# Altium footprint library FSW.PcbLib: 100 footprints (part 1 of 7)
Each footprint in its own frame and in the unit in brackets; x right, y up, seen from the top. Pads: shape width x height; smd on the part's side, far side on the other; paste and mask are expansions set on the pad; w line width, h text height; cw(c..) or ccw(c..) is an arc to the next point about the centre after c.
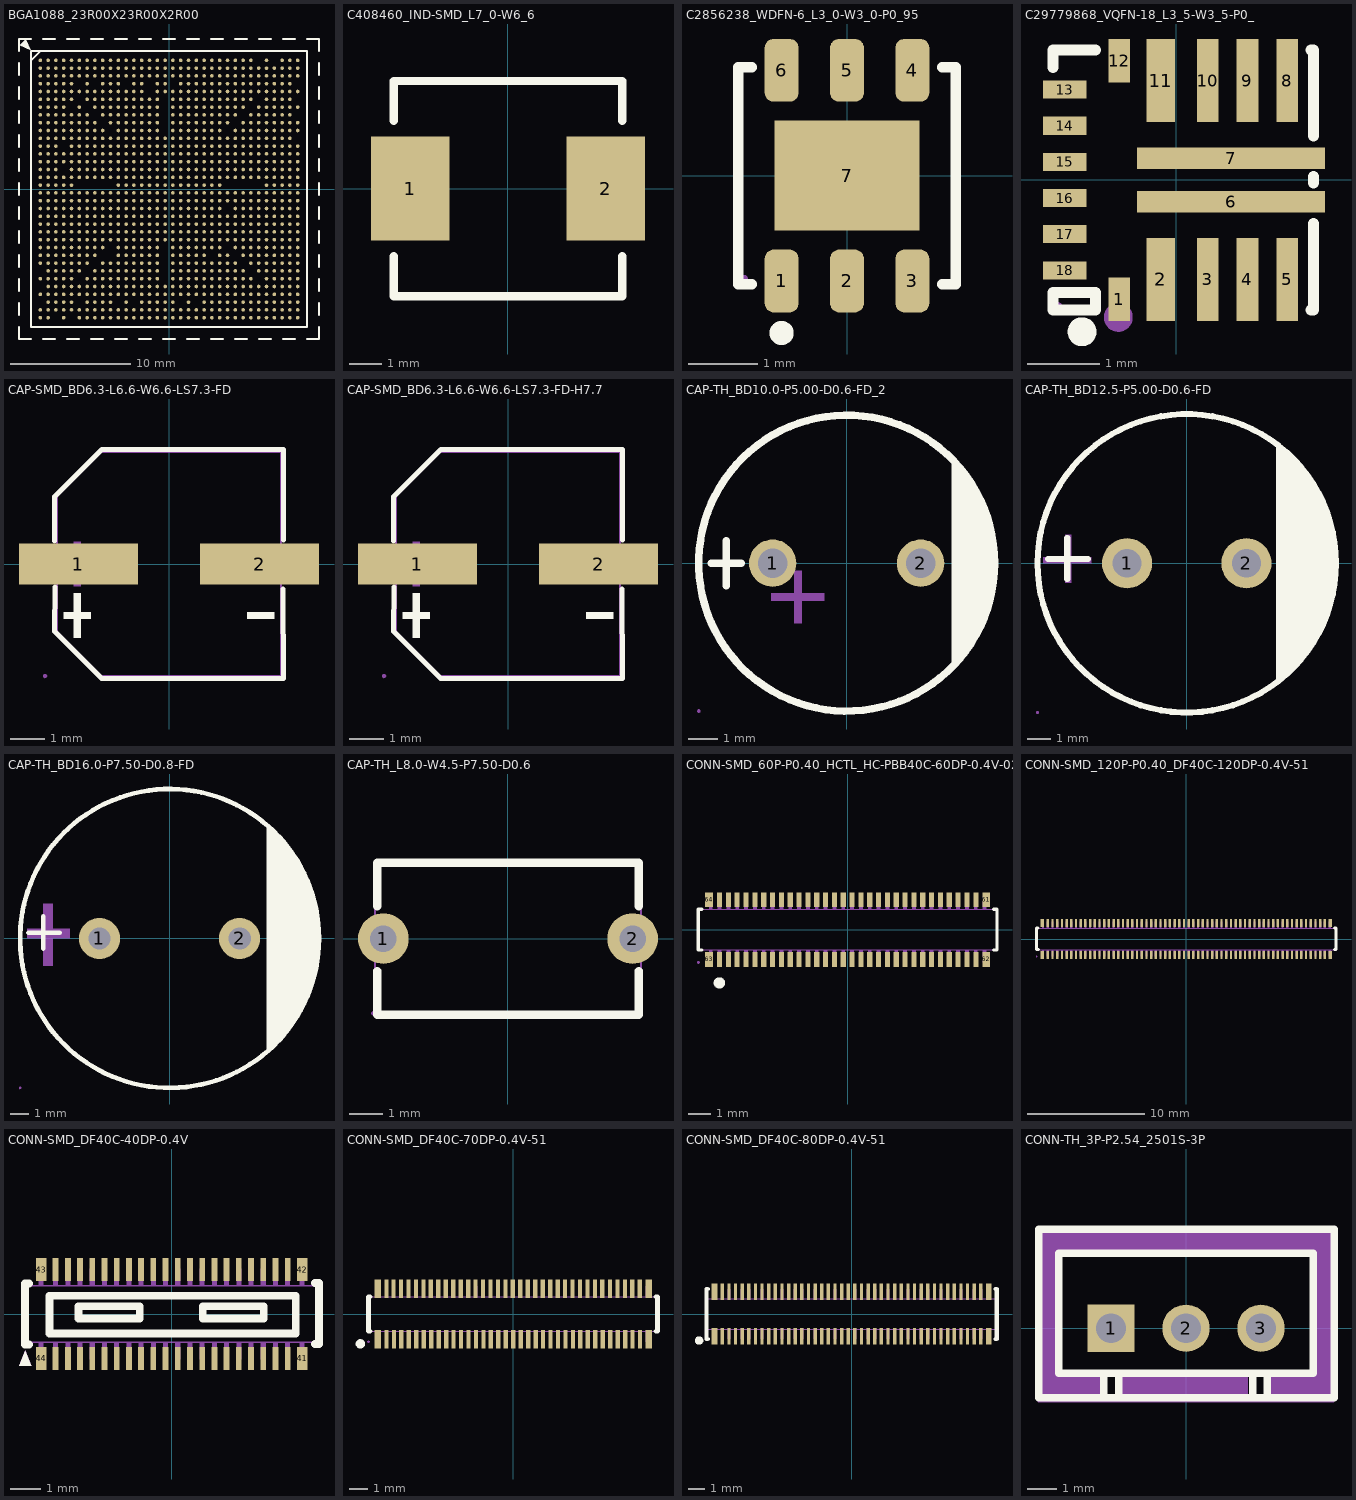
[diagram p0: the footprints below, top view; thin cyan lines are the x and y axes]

## BGA1088_23R00X23R00X2R00 [mm]
pads (1088):
  round 0.3 smd paste+0.102 mask+0.025: A1(-10.725,10.725) A2(-10.075,10.725) A3(-9.425,10.725) A4(-8.775,10.725) A5(-8.125,10.725) A6(-7.475,10.725) A7(-6.825,10.725) A8(-6.175,10.725) A9(-5.525,10.725) A10(-4.875,10.725) A11(-4.225,10.725) A12(-3.575,10.725) A13(-2.925,10.725) A14(-2.275,10.725) A15(-1.625,10.725) A16(-0.975,10.725) A17(-0.325,10.725) A18(0.325,10.725) A19(0.975,10.725) A20(1.625,10.725) A21(2.275,10.725) A22(2.925,10.725) A23(3.575,10.725) A24(4.225,10.725) A25(4.875,10.725) A26(5.525,10.725) A27(6.175,10.725) A28(6.825,10.725) A30(8.125,10.725) A32(9.425,10.725) A33(10.075,10.725) A34(10.725,10.725) AA1(-10.725,-2.275) AA2(-10.075,-2.275) AA3(-9.425,-2.275) AA4(-8.775,-2.275) AA5(-8.125,-2.275) AA6(-7.475,-2.275) AA7(-6.825,-2.275) AA8(-6.175,-2.275) AA9(-5.525,-2.275) AA10(-4.875,-2.275) AA11(-4.225,-2.275) AA12(-3.575,-2.275) AA13(-2.925,-2.275) AA14(-2.275,-2.275) AA15(-1.625,-2.275) AA16(-0.975,-2.275) AA17(-0.325,-2.275) AA18(0.325,-2.275) AA19(0.975,-2.275) AA20(1.625,-2.275) AA21(2.275,-2.275) AA22(2.925,-2.275) AA23(3.575,-2.275) AA24(4.225,-2.275) AA25(4.875,-2.275) AA26(5.525,-2.275) AA27(6.175,-2.275) AA28(6.825,-2.275) AA29(7.475,-2.275) AA30(8.125,-2.275) AA31(8.775,-2.275) AA32(9.425,-2.275) AA33(10.075,-2.275) AA34(10.725,-2.275) AB1(-10.725,-2.925) AB2(-10.075,-2.925) AB3(-9.425,-2.925) AB4(-8.775,-2.925) AB5(-8.125,-2.925) AB6(-7.475,-2.925) AB7(-6.825,-2.925) AB8(-6.175,-2.925) AB9(-5.525,-2.925) AB10(-4.875,-2.925) AB11(-4.225,-2.925) AB12(-3.575,-2.925) AB13(-2.925,-2.925) AB14(-2.275,-2.925) AB15(-1.625,-2.925) AB16(-0.975,-2.925) AB17(-0.325,-2.925) AB18(0.325,-2.925) AB19(0.975,-2.925) AB20(1.625,-2.925) AB21(2.275,-2.925) AB22(2.925,-2.925) AB23(3.575,-2.925) AB24(4.225,-2.925) AB25(4.875,-2.925) AB26(5.525,-2.925) AB27(6.175,-2.925) AB28(6.825,-2.925) AB29(7.475,-2.925) AB30(8.125,-2.925) AB31(8.775,-2.925) AB32(9.425,-2.925) AB33(10.075,-2.925) AB34(10.725,-2.925) AC1(-10.725,-3.575) AC2(-10.075,-3.575) AC3(-9.425,-3.575) AC4(-8.775,-3.575) AC5(-8.125,-3.575) AC6(-7.475,-3.575) AC7(-6.825,-3.575) AC8(-6.175,-3.575) AC9(-5.525,-3.575) AC10(-4.875,-3.575) AC11(-4.225,-3.575) AC12(-3.575,-3.575) AC13(-2.925,-3.575) AC14(-2.275,-3.575) AC15(-1.625,-3.575) AC16(-0.975,-3.575) AC17(-0.325,-3.575) AC18(0.325,-3.575) AC19(0.975,-3.575) AC20(1.625,-3.575) AC21(2.275,-3.575) AC22(2.925,-3.575) AC23(3.575,-3.575) AC24(4.225,-3.575) AC25(4.875,-3.575) AC26(5.525,-3.575) AC27(6.175,-3.575) AC28(6.825,-3.575) AC29(7.475,-3.575) AC30(8.125,-3.575) AC31(8.775,-3.575) AC32(9.425,-3.575) AC33(10.075,-3.575) AC34(10.725,-3.575) AD1(-10.725,-4.225) AD2(-10.075,-4.225) AD3(-9.425,-4.225) AD4(-8.775,-4.225) AD5(-8.125,-4.225) AD6(-7.475,-4.225) AD7(-6.825,-4.225) AD8(-6.175,-4.225) AD9(-5.525,-4.225) AD10(-4.875,-4.225) AD11(-4.225,-4.225) AD12(-3.575,-4.225) AD13(-2.925,-4.225) AD14(-2.275,-4.225) AD15(-1.625,-4.225) AD16(-0.975,-4.225) AD17(-0.325,-4.225) AD18(0.325,-4.225) AD19(0.975,-4.225) AD20(1.625,-4.225) AD21(2.275,-4.225) AD22(2.925,-4.225) AD23(3.575,-4.225) AD24(4.225,-4.225) AD25(4.875,-4.225) AD26(5.525,-4.225) AD27(6.175,-4.225) AD28(6.825,-4.225) AD29(7.475,-4.225) AD30(8.125,-4.225) AD31(8.775,-4.225) AD32(9.425,-4.225) AD33(10.075,-4.225) AD34(10.725,-4.225) AE1(-10.725,-4.875) AE2(-10.075,-4.875) AE3(-9.425,-4.875) AE4(-8.775,-4.875) AE5(-8.125,-4.875) AE6(-7.475,-4.875) AE7(-6.825,-4.875) AE8(-6.175,-4.875) AE9(-5.525,-4.875) AE11(-4.225,-4.875) AE12(-3.575,-4.875) AE13(-2.925,-4.875) AE14(-2.275,-4.875) AE15(-1.625,-4.875) AE16(-0.975,-4.875) AE18(0.325,-4.875) AE19(0.975,-4.875) AE20(1.625,-4.875) AE21(2.275,-4.875) AE22(2.925,-4.875) AE23(3.575,-4.875) AE24(4.225,-4.875) AE26(5.525,-4.875) AE27(6.175,-4.875) AE28(6.825,-4.875) AE29(7.475,-4.875) AE30(8.125,-4.875) AE31(8.775,-4.875) AE32(9.425,-4.875) AE33(10.075,-4.875) AE34(10.725,-4.875) AF1(-10.725,-5.525) AF2(-10.075,-5.525) AF3(-9.425,-5.525) AF4(-8.775,-5.525) AF5(-8.125,-5.525) AF6(-7.475,-5.525) AF7(-6.825,-5.525) AF8(-6.175,-5.525) AF11(-4.225,-5.525) AF12(-3.575,-5.525) AF13(-2.925,-5.525) AF14(-2.275,-5.525) AF15(-1.625,-5.525) AF16(-0.975,-5.525) AF18(0.325,-5.525) AF19(0.975,-5.525) AF20(1.625,-5.525) AF21(2.275,-5.525) AF22(2.925,-5.525) AF24(4.225,-5.525) AF25(4.875,-5.525) AF27(6.175,-5.525) AF28(6.825,-5.525) AF29(7.475,-5.525) AF30(8.125,-5.525) AF31(8.775,-5.525) AF32(9.425,-5.525) AF33(10.075,-5.525) AF34(10.725,-5.525) AG1(-10.725,-6.175) AG2(-10.075,-6.175) AG3(-9.425,-6.175) AG4(-8.775,-6.175) AG5(-8.125,-6.175) AG6(-7.475,-6.175) AG7(-6.825,-6.175) AG9(-5.525,-6.175) AG10(-4.875,-6.175) AG11(-4.225,-6.175) AG12(-3.575,-6.175) AG13(-2.925,-6.175) AG14(-2.275,-6.175) AG15(-1.625,-6.175) AG16(-0.975,-6.175) AG18(0.325,-6.175) AG19(0.975,-6.175) AG20(1.625,-6.175) AG21(2.275,-6.175) AG22(2.925,-6.175) AG23(3.575,-6.175) AG24(4.225,-6.175) AG25(4.875,-6.175) AG26(5.525,-6.175) AG28(6.825,-6.175) AG29(7.475,-6.175) AG30(8.125,-6.175) AG31(8.775,-6.175) AG32(9.425,-6.175) AG33(10.075,-6.175) AG34(10.725,-6.175) AH2(-10.075,-6.825) AH3(-9.425,-6.825) AH4(-8.775,-6.825) AH5(-8.125,-6.825) AH6(-7.475,-6.825) AH8(-6.175,-6.825) AH9(-5.525,-6.825) AH10(-4.875,-6.825) AH11(-4.225,-6.825) AH12(-3.575,-6.825) AH13(-2.925,-6.825) AH14(-2.275,-6.825) AH15(-1.625,-6.825) AH16(-0.975,-6.825) AH18(0.325,-6.825) AH19(0.975,-6.825) AH20(1.625,-6.825) AH21(2.275,-6.825) AH22(2.925,-6.825) AH23(3.575,-6.825) AH24(4.225,-6.825) AH25(4.875,-6.825) AH26(5.525,-6.825) AH27(6.175,-6.825) AH29(7.475,-6.825) AH30(8.125,-6.825) AH31(8.775,-6.825) AH32(9.425,-6.825) AH33(10.075,-6.825) AH34(10.725,-6.825) AJ1(-10.725,-7.475) AJ2(-10.075,-7.475) AJ3(-9.425,-7.475) AJ4(-8.775,-7.475) AJ5(-8.125,-7.475) AJ7(-6.825,-7.475) AJ8(-6.175,-7.475) AJ9(-5.525,-7.475) AJ10(-4.875,-7.475) AJ11(-4.225,-7.475) AJ12(-3.575,-7.475) AJ13(-2.925,-7.475) AJ14(-2.275,-7.475) AJ15(-1.625,-7.475) AJ16(-0.975,-7.475) AJ18(0.325,-7.475) AJ19(0.975,-7.475) AJ20(1.625,-7.475) AJ21(2.275,-7.475) AJ22(2.925,-7.475) AJ23(3.575,-7.475) AJ24(4.225,-7.475) AJ25(4.875,-7.475) AJ26(5.525,-7.475) AJ27(6.175,-7.475) AJ28(6.825,-7.475) AJ30(8.125,-7.475) AJ31(8.775,-7.475) AJ32(9.425,-7.475) AJ33(10.075,-7.475) AJ34(10.725,-7.475) AK2(-10.075,-8.125) AK3(-9.425,-8.125) AK4(-8.775,-8.125) AK5(-8.125,-8.125) AK6(-7.475,-8.125) AK7(-6.825,-8.125) AK8(-6.175,-8.125) AK9(-5.525,-8.125) AK10(-4.875,-8.125) AK11(-4.225,-8.125) AK12(-3.575,-8.125) AK13(-2.925,-8.125) AK14(-2.275,-8.125) AK15(-1.625,-8.125) AK16(-0.975,-8.125) AK17(-0.325,-8.125) AK18(0.325,-8.125) AK19(0.975,-8.125) AK20(1.625,-8.125) AK21(2.275,-8.125) AK22(2.925,-8.125) AK23(3.575,-8.125) AK24(4.225,-8.125) AK25(4.875,-8.125) AK26(5.525,-8.125) AK27(6.175,-8.125) AK28(6.825,-8.125) AK29(7.475,-8.125) AK30(8.125,-8.125) AK31(8.775,-8.125) AK32(9.425,-8.125) AK33(10.075,-8.125) AK34(10.725,-8.125) AL1(-10.725,-8.775) AL2(-10.075,-8.775) AL3(-9.425,-8.775) AL4(-8.775,-8.775) AL5(-8.125,-8.775) AL6(-7.475,-8.775) AL7(-6.825,-8.775) AL8(-6.175,-8.775) AL9(-5.525,-8.775) AL10(-4.875,-8.775) AL11(-4.225,-8.775) AL12(-3.575,-8.775) AL13(-2.925,-8.775) AL14(-2.275,-8.775) AL15(-1.625,-8.775) AL16(-0.975,-8.775) AL17(-0.325,-8.775) AL18(0.325,-8.775) AL19(0.975,-8.775) AL20(1.625,-8.775) AL21(2.275,-8.775) AL22(2.925,-8.775) AL23(3.575,-8.775) AL24(4.225,-8.775) AL25(4.875,-8.775) AL26(5.525,-8.775) AL27(6.175,-8.775) AL28(6.825,-8.775) AL29(7.475,-8.775) AL30(8.125,-8.775) AL31(8.775,-8.775) AL32(9.425,-8.775) AL33(10.075,-8.775) AL34(10.725,-8.775) AM2(-10.075,-9.425) AM3(-9.425,-9.425) AM4(-8.775,-9.425) AM5(-8.125,-9.425) AM7(-6.825,-9.425) AM8(-6.175,-9.425) AM9(-5.525,-9.425) AM10(-4.875,-9.425) AM12(-3.575,-9.425) AM14(-2.275,-9.425) AM15(-1.625,-9.425) AM16(-0.975,-9.425) AM17(-0.325,-9.425) AM18(0.325,-9.425) AM20(1.625,-9.425) AM22(2.925,-9.425) AM23(3.575,-9.425) AM24(4.225,-9.425) AM25(4.875,-9.425) AM26(5.525,-9.425) AM27(6.175,-9.425) AM28(6.825,-9.425) AM29(7.475,-9.425) AM30(8.125,-9.425) AM31(8.775,-9.425) AM32(9.425,-9.425) AM33(10.075,-9.425) AM34(10.725,-9.425) AN1(-10.725,-10.075) AN2(-10.075,-10.075) AN3(-9.425,-10.075) AN4(-8.775,-10.075) AN5(-8.125,-10.075) AN6(-7.475,-10.075) AN7(-6.825,-10.075) AN8(-6.175,-10.075) AN9(-5.525,-10.075) AN10(-4.875,-10.075) AN11(-4.225,-10.075) AN12(-3.575,-10.075) AN13(-2.925,-10.075) AN14(-2.275,-10.075) AN15(-1.625,-10.075) AN16(-0.975,-10.075) AN17(-0.325,-10.075) AN18(0.325,-10.075) AN19(0.975,-10.075) AN20(1.625,-10.075) AN21(2.275,-10.075) AN22(2.925,-10.075) AN23(3.575,-10.075) AN24(4.225,-10.075) AN25(4.875,-10.075) AN26(5.525,-10.075) AN27(6.175,-10.075) AN28(6.825,-10.075) AN29(7.475,-10.075) AN30(8.125,-10.075) AN31(8.775,-10.075) AN32(9.425,-10.075) AN33(10.075,-10.075) AN34(10.725,-10.075) AP1(-10.725,-10.725) AP2(-10.075,-10.725) AP4(-8.775,-10.725) AP6(-7.475,-10.725) AP7(-6.825,-10.725) AP8(-6.175,-10.725) AP9(-5.525,-10.725) AP10(-4.875,-10.725) AP11(-4.225,-10.725) AP12(-3.575,-10.725) AP13(-2.925,-10.725) AP14(-2.275,-10.725) AP15(-1.625,-10.725) AP16(-0.975,-10.725) AP17(-0.325,-10.725) AP18(0.325,-10.725) AP19(0.975,-10.725) AP20(1.625,-10.725) AP21(2.275,-10.725) AP22(2.925,-10.725) AP23(3.575,-10.725) AP24(4.225,-10.725) AP25(4.875,-10.725) AP26(5.525,-10.725) AP27(6.175,-10.725) AP28(6.825,-10.725) AP29(7.475,-10.725) AP30(8.125,-10.725) AP31(8.775,-10.725) AP32(9.425,-10.725) AP33(10.075,-10.725) AP34(10.725,-10.725) B1(-10.725,10.075) B2(-10.075,10.075) B3(-9.425,10.075) B4(-8.775,10.075) B5(-8.125,10.075) B6(-7.475,10.075) B7(-6.825,10.075) B8(-6.175,10.075) B9(-5.525,10.075) B10(-4.875,10.075) B11(-4.225,10.075) B12(-3.575,10.075) B13(-2.925,10.075) B14(-2.275,10.075) B15(-1.625,10.075) B16(-0.975,10.075) B17(-0.325,10.075) B18(0.325,10.075) B19(0.975,10.075) B20(1.625,10.075) B21(2.275,10.075) B22(2.925,10.075) B23(3.575,10.075) B24(4.225,10.075) B25(4.875,10.075) B26(5.525,10.075) B27(6.175,10.075) B28(6.825,10.075) B29(7.475,10.075) B30(8.125,10.075) B31(8.775,10.075) B32(9.425,10.075) B33(10.075,10.075) B34(10.725,10.075) C1(-10.725,9.425) C2(-10.075,9.425) C3(-9.425,9.425) C4(-8.775,9.425) C5(-8.125,9.425) C6(-7.475,9.425) C7(-6.825,9.425) C8(-6.175,9.425) C9(-5.525,9.425) C10(-4.875,9.425) C11(-4.225,9.425) C12(-3.575,9.425) C13(-2.925,9.425) C14(-2.275,9.425) C15(-1.625,9.425) C16(-0.975,9.425) C17(-0.325,9.425) C18(0.325,9.425) C19(0.975,9.425) C20(1.625,9.425) C21(2.275,9.425) C22(2.925,9.425) C23(3.575,9.425) C24(4.225,9.425) C25(4.875,9.425) C26(5.525,9.425) C27(6.175,9.425) C28(6.825,9.425) C29(7.475,9.425) C30(8.125,9.425) C31(8.775,9.425) C32(9.425,9.425) C33(10.075,9.425) C34(10.725,9.425) D1(-10.725,8.775) D2(-10.075,8.775) D3(-9.425,8.775) D4(-8.775,8.775) D5(-8.125,8.775) D7(-6.825,8.775) D9(-5.525,8.775) D10(-4.875,8.775) D11(-4.225,8.775) D13(-2.925,8.775) D14(-2.275,8.775) D16(-0.975,8.775) D17(-0.325,8.775) D19(0.975,8.775) D20(1.625,8.775) D21(2.275,8.775) D22(2.925,8.775) D23(3.575,8.775) D24(4.225,8.775) D25(4.875,8.775) D26(5.525,8.775) D27(6.175,8.775) D28(6.825,8.775) D29(7.475,8.775) D30(8.125,8.775) D31(8.775,8.775) D32(9.425,8.775) D33(10.075,8.775) E1(-10.725,8.125) E2(-10.075,8.125) E3(-9.425,8.125) E4(-8.775,8.125) E5(-8.125,8.125) E6(-7.475,8.125) E7(-6.825,8.125) E8(-6.175,8.125) E9(-5.525,8.125) E10(-4.875,8.125) E11(-4.225,8.125) E12(-3.575,8.125) E13(-2.925,8.125) E14(-2.275,8.125) E16(-0.975,8.125) E17(-0.325,8.125) E18(0.325,8.125) E19(0.975,8.125) E20(1.625,8.125) E21(2.275,8.125) E22(2.925,8.125) E23(3.575,8.125) E24(4.225,8.125) E25(4.875,8.125) E26(5.525,8.125) E27(6.175,8.125) E28(6.825,8.125) E29(7.475,8.125) E30(8.125,8.125) E31(8.775,8.125) E32(9.425,8.125) E33(10.075,8.125) E34(10.725,8.125) F1(-10.725,7.475) F2(-10.075,7.475) F3(-9.425,7.475) F4(-8.775,7.475) F5(-8.125,7.475) F7(-6.825,7.475) F8(-6.175,7.475) F9(-5.525,7.475) F10(-4.875,7.475) F11(-4.225,7.475) F12(-3.575,7.475) F13(-2.925,7.475) F14(-2.275,7.475) F15(-1.625,7.475) F16(-0.975,7.475) F18(0.325,7.475) F19(0.975,7.475) F20(1.625,7.475) F21(2.275,7.475) F22(2.925,7.475) F23(3.575,7.475) F24(4.225,7.475) F25(4.875,7.475) F26(5.525,7.475) F27(6.175,7.475) F28(6.825,7.475) F30(8.125,7.475) F31(8.775,7.475) F32(9.425,7.475) F33(10.075,7.475) G1(-10.725,6.825) G2(-10.075,6.825) G3(-9.425,6.825) G4(-8.775,6.825) G6(-7.475,6.825) G8(-6.175,6.825) G9(-5.525,6.825) G10(-4.875,6.825) G11(-4.225,6.825) G12(-3.575,6.825) G13(-2.925,6.825) G14(-2.275,6.825) G15(-1.625,6.825) G16(-0.975,6.825) G18(0.325,6.825) G19(0.975,6.825) G20(1.625,6.825) G21(2.275,6.825) G22(2.925,6.825) G23(3.575,6.825) G24(4.225,6.825) G25(4.875,6.825) G26(5.525,6.825) G27(6.175,6.825) G29(7.475,6.825) G30(8.125,6.825) G31(8.775,6.825) G32(9.425,6.825) G33(10.075,6.825) G34(10.725,6.825) H1(-10.725,6.175) H2(-10.075,6.175) H3(-9.425,6.175) H4(-8.775,6.175) H5(-8.125,6.175) H6(-7.475,6.175) H7(-6.825,6.175) H9(-5.525,6.175) H10(-4.875,6.175) H11(-4.225,6.175) H12(-3.575,6.175) H13(-2.925,6.175) H14(-2.275,6.175) H15(-1.625,6.175) H16(-0.975,6.175) H18(0.325,6.175) H19(0.975,6.175) H20(1.625,6.175) H21(2.275,6.175) H22(2.925,6.175) H23(3.575,6.175) H24(4.225,6.175) H25(4.875,6.175) H26(5.525,6.175) H28(6.825,6.175) H29(7.475,6.175) H30(8.125,6.175) H31(8.775,6.175) H32(9.425,6.175) H33(10.075,6.175) J1(-10.725,5.525) J2(-10.075,5.525) J3(-9.425,5.525) J4(-8.775,5.525) J5(-8.125,5.525) J6(-7.475,5.525) J7(-6.825,5.525) J8(-6.175,5.525) J10(-4.875,5.525) J11(-4.225,5.525) J12(-3.575,5.525) J13(-2.925,5.525) J14(-2.275,5.525) J15(-1.625,5.525) J16(-0.975,5.525) J18(0.325,5.525) J19(0.975,5.525) J20(1.625,5.525) J21(2.275,5.525) J22(2.925,5.525) J23(3.575,5.525) J24(4.225,5.525) J25(4.875,5.525) J27(6.175,5.525) J28(6.825,5.525) J29(7.475,5.525) J30(8.125,5.525) J31(8.775,5.525) J32(9.425,5.525) J33(10.075,5.525) J34(10.725,5.525) K1(-10.725,4.875) K2(-10.075,4.875) K3(-9.425,4.875) K4(-8.775,4.875) K5(-8.125,4.875) K6(-7.475,4.875) K7(-6.825,4.875) K8(-6.175,4.875) K9(-5.525,4.875) K11(-4.225,4.875) K12(-3.575,4.875) K13(-2.925,4.875) K14(-2.275,4.875) K15(-1.625,4.875) K16(-0.975,4.875) K18(0.325,4.875) K19(0.975,4.875) K20(1.625,4.875) K21(2.275,4.875) K22(2.925,4.875) K23(3.575,4.875) K24(4.225,4.875) K26(5.525,4.875) K27(6.175,4.875) K28(6.825,4.875) K29(7.475,4.875) K30(8.125,4.875) K31(8.775,4.875) K32(9.425,4.875) K33(10.075,4.875) K34(10.725,4.875) L1(-10.725,4.225) L2(-10.075,4.225) L3(-9.425,4.225) L4(-8.775,4.225) L5(-8.125,4.225) L6(-7.475,4.225) L7(-6.825,4.225) L8(-6.175,4.225) L9(-5.525,4.225) L10(-4.875,4.225) L11(-4.225,4.225) L12(-3.575,4.225) L13(-2.925,4.225) L14(-2.275,4.225) L15(-1.625,4.225) L16(-0.975,4.225) L17(-0.325,4.225) L18(0.325,4.225) L19(0.975,4.225) L20(1.625,4.225) L21(2.275,4.225) L22(2.925,4.225) L23(3.575,4.225) L24(4.225,4.225) L25(4.875,4.225) L26(5.525,4.225) L27(6.175,4.225) L28(6.825,4.225) L29(7.475,4.225) L30(8.125,4.225) L31(8.775,4.225) L32(9.425,4.225) L33(10.075,4.225) M1(-10.725,3.575) M2(-10.075,3.575) M3(-9.425,3.575) M5(-8.125,3.575) M6(-7.475,3.575) M7(-6.825,3.575) M8(-6.175,3.575) M9(-5.525,3.575) M10(-4.875,3.575) M11(-4.225,3.575) M12(-3.575,3.575) M13(-2.925,3.575) M14(-2.275,3.575) M15(-1.625,3.575) M16(-0.975,3.575) M17(-0.325,3.575) M18(0.325,3.575) M19(0.975,3.575) M20(1.625,3.575) M21(2.275,3.575) M22(2.925,3.575) M23(3.575,3.575) M24(4.225,3.575) M25(4.875,3.575) M26(5.525,3.575) M27(6.175,3.575) M28(6.825,3.575) M29(7.475,3.575) M30(8.125,3.575) M31(8.775,3.575) M32(9.425,3.575) M33(10.075,3.575) M34(10.725,3.575) N1(-10.725,2.925) N2(-10.075,2.925) N3(-9.425,2.925) N4(-8.775,2.925) N5(-8.125,2.925) N6(-7.475,2.925) N7(-6.825,2.925) N8(-6.175,2.925) N9(-5.525,2.925) N10(-4.875,2.925) N11(-4.225,2.925) N12(-3.575,2.925) N13(-2.925,2.925) N14(-2.275,2.925) N15(-1.625,2.925) N16(-0.975,2.925) N17(-0.325,2.925) N18(0.325,2.925) N19(0.975,2.925) N20(1.625,2.925) N21(2.275,2.925) N22(2.925,2.925) N23(3.575,2.925) N24(4.225,2.925) N25(4.875,2.925) N26(5.525,2.925) N27(6.175,2.925) N28(6.825,2.925) N29(7.475,2.925) N30(8.125,2.925) N31(8.775,2.925) N32(9.425,2.925) N33(10.075,2.925) N34(10.725,2.925) P1(-10.725,2.275) P2(-10.075,2.275) P3(-9.425,2.275) P4(-8.775,2.275) P5(-8.125,2.275) P6(-7.475,2.275) P7(-6.825,2.275) P8(-6.175,2.275) P9(-5.525,2.275) P10(-4.875,2.275) P11(-4.225,2.275) P12(-3.575,2.275) P13(-2.925,2.275) P14(-2.275,2.275) P15(-1.625,2.275) P16(-0.975,2.275) P17(-0.325,2.275) P18(0.325,2.275) P19(0.975,2.275) P20(1.625,2.275) P21(2.275,2.275) P22(2.925,2.275) P23(3.575,2.275) P24(4.225,2.275) P25(4.875,2.275) P26(5.525,2.275) P27(6.175,2.275) P28(6.825,2.275) P29(7.475,2.275) P30(8.125,2.275) P31(8.775,2.275) P32(9.425,2.275) P33(10.075,2.275) P34(10.725,2.275) R1(-10.725,1.625) R2(-10.075,1.625) R3(-9.425,1.625) R5(-8.125,1.625) R6(-7.475,1.625) R7(-6.825,1.625) R8(-6.175,1.625) R9(-5.525,1.625) R10(-4.875,1.625) R11(-4.225,1.625) R12(-3.575,1.625) R13(-2.925,1.625) R14(-2.275,1.625) R15(-1.625,1.625) R16(-0.975,1.625) R17(-0.325,1.625) R18(0.325,1.625) R19(0.975,1.625) R20(1.625,1.625) R21(2.275,1.625) R22(2.925,1.625) R23(3.575,1.625) R24(4.225,1.625) R25(4.875,1.625) R26(5.525,1.625) R27(6.175,1.625) R28(6.825,1.625) R29(7.475,1.625) R30(8.125,1.625) R31(8.775,1.625) R32(9.425,1.625) R33(10.075,1.625) R34(10.725,1.625) T1(-10.725,0.975) T2(-10.075,0.975) T3(-9.425,0.975) T4(-8.775,0.975) T5(-8.125,0.975) T6(-7.475,0.975) T7(-6.825,0.975) T8(-6.175,0.975) T9(-5.525,0.975) T10(-4.875,0.975) T11(-4.225,0.975) T12(-3.575,0.975) T13(-2.925,0.975) T14(-2.275,0.975) T15(-1.625,0.975) T16(-0.975,0.975) T17(-0.325,0.975) T18(0.325,0.975) T19(0.975,0.975) T20(1.625,0.975) T21(2.275,0.975) T22(2.925,0.975) T23(3.575,0.975) T24(4.225,0.975) T25(4.875,0.975) T26(5.525,0.975) T27(6.175,0.975) T28(6.825,0.975) T29(7.475,0.975) T30(8.125,0.975) T31(8.775,0.975) T32(9.425,0.975) T33(10.075,0.975) T34(10.725,0.975) U1(-10.725,0.325) U2(-10.075,0.325) U3(-9.425,0.325) U4(-8.775,0.325) U5(-8.125,0.325) U11(-4.225,0.325) U12(-3.575,0.325) U13(-2.925,0.325) U14(-2.275,0.325) U15(-1.625,0.325) U16(-0.975,0.325) U17(-0.325,0.325) U18(0.325,0.325) U19(0.975,0.325) U20(1.625,0.325) U21(2.275,0.325) U22(2.925,0.325) U23(3.575,0.325) U24(4.225,0.325) U30(8.125,0.325) U31(8.775,0.325) U32(9.425,0.325) U33(10.075,0.325) U34(10.725,0.325) V1(-10.725,-0.325) V2(-10.075,-0.325) V3(-9.425,-0.325) V4(-8.775,-0.325) V5(-8.125,-0.325) V6(-7.475,-0.325) V7(-6.825,-0.325) V8(-6.175,-0.325) V9(-5.525,-0.325) V10(-4.875,-0.325) V11(-4.225,-0.325) V12(-3.575,-0.325) V13(-2.925,-0.325) V14(-2.275,-0.325) V15(-1.625,-0.325) V16(-0.975,-0.325) V17(-0.325,-0.325) V18(0.325,-0.325) V19(0.975,-0.325) V20(1.625,-0.325) V21(2.275,-0.325) V22(2.925,-0.325) V23(3.575,-0.325) V24(4.225,-0.325) V25(4.875,-0.325) V26(5.525,-0.325) V27(6.175,-0.325) V28(6.825,-0.325) V29(7.475,-0.325) V30(8.125,-0.325) V31(8.775,-0.325) V32(9.425,-0.325) V33(10.075,-0.325) V34(10.725,-0.325) W1(-10.725,-0.975) W2(-10.075,-0.975) W3(-9.425,-0.975) W4(-8.775,-0.975) W5(-8.125,-0.975) W6(-7.475,-0.975) W7(-6.825,-0.975) W8(-6.175,-0.975) W9(-5.525,-0.975) W10(-4.875,-0.975) W11(-4.225,-0.975) W12(-3.575,-0.975) W13(-2.925,-0.975) W14(-2.275,-0.975) W15(-1.625,-0.975) W16(-0.975,-0.975) W17(-0.325,-0.975) W18(0.325,-0.975) W19(0.975,-0.975) W20(1.625,-0.975) W21(2.275,-0.975) W22(2.925,-0.975) W23(3.575,-0.975) W24(4.225,-0.975) W25(4.875,-0.975) W26(5.525,-0.975) W27(6.175,-0.975) W28(6.825,-0.975) W29(7.475,-0.975) W30(8.125,-0.975) W31(8.775,-0.975) W32(9.425,-0.975) W33(10.075,-0.975) W34(10.725,-0.975) Y1(-10.725,-1.625) Y2(-10.075,-1.625) Y3(-9.425,-1.625) Y4(-8.775,-1.625) Y5(-8.125,-1.625) Y6(-7.475,-1.625) Y7(-6.825,-1.625) Y8(-6.175,-1.625) Y9(-5.525,-1.625) Y10(-4.875,-1.625) Y11(-4.225,-1.625) Y12(-3.575,-1.625) Y13(-2.925,-1.625) Y14(-2.275,-1.625) Y15(-1.625,-1.625) Y16(-0.975,-1.625) Y17(-0.325,-1.625) Y18(0.325,-1.625) Y19(0.975,-1.625) Y20(1.625,-1.625) Y21(2.275,-1.625) Y22(2.925,-1.625) Y23(3.575,-1.625) Y24(4.225,-1.625) Y26(5.525,-1.625) Y27(6.175,-1.625) Y28(6.825,-1.625) Y29(7.475,-1.625) Y30(8.125,-1.625) Y31(8.775,-1.625) Y32(9.425,-1.625) Y33(10.075,-1.625) Y34(10.725,-1.625)
Top Overlay:
  region: -12.437,11.974 -11.531,11.563 -11.943,12.468
  lines w0.127: -12.5,-11.5 -12.5,-12.5 -11.5,-12.5 ; -12.5,-10.5 -12.5,-9.5 ; -12.5,-8.5 -12.5,-7.5 ; -12.5,-6.5 -12.5,-5.5 ; -12.5,-4.5 -12.5,-3.5 ; -12.5,-2.5 -12.5,-1.5 ; -12.5,-0.5 -12.5,0.5 ; -12.5,1.5 -12.5,2.5 ; -12.5,3.5 -12.5,4.5 ; -12.5,5.5 -12.5,6.5 ; -12.5,7.5 -12.5,8.5 ; -12.5,9.5 -12.5,10.5 ; -12.5,11.5 -12.5,12.5 -11.5,12.5 ; -10.5,-12.5 -9.5,-12.5 ; -10.5,12.5 -9.5,12.5 ; -8.5,-12.5 -7.5,-12.5 ; -8.5,12.5 -7.5,12.5 ; -6.5,-12.5 -5.5,-12.5 ; -6.5,12.5 -5.5,12.5 ; -4.5,-12.5 -3.5,-12.5 ; -4.5,12.5 -3.5,12.5 ; -2.5,-12.5 -1.5,-12.5 ; -2.5,12.5 -1.5,12.5 ; -0.5,-12.5 0.5,-12.5 ; -0.5,12.5 0.5,12.5 ; 1.5,-12.5 2.5,-12.5 ; 1.5,12.5 2.5,12.5 ; 3.5,-12.5 4.5,-12.5 ; 3.5,12.5 4.5,12.5 ; 5.5,-12.5 6.5,-12.5 ; 5.5,12.5 6.5,12.5 ; 7.5,-12.5 8.5,-12.5 ; 7.5,12.5 8.5,12.5 ; 9.5,-12.5 10.5,-12.5 ; 9.5,12.5 10.5,12.5 ; 11.5,-12.5 12.5,-12.5 12.5,-11.5 ; 11.5,12.5 12.5,12.5 12.5,11.5 ; 12.5,-10.5 12.5,-9.5 ; 12.5,-8.5 12.5,-7.5 ; 12.5,-6.5 12.5,-5.5 ; 12.5,-4.5 12.5,-3.5 ; 12.5,-2.5 12.5,-1.5 ; 12.5,-0.5 12.5,0.5 ; 12.5,1.5 12.5,2.5 ; 12.5,3.5 12.5,4.5 ; 12.5,5.5 12.5,6.5 ; 12.5,7.5 12.5,8.5 ; 12.5,9.5 12.5,10.5
  lines w0.15: -11.463,10.733 -10.731,11.465 ; -11.5,-11.5 -11.5,11.5 11.5,11.5 11.5,-11.5 -11.5,-11.5
3D body "FCBGA-1088_L23.0-W23.0-P0.65-TL_RK3588.step": height 1.62, standoff 0.01, extent -11.5,-11.5 11.5,11.5

## C408460_IND-SMD_L7_0-W6_6 [mm] "MWSA0605S-R68MT [C408460]"
pads (2):
  rect 2.4x3.2 smd: 1(-3,0) 2(3,0)
Top Overlay:
  lines w0.254: -3.5,-2.081 -3.5,-3.3 -3.49,-3.3 3.5,-3.3 3.5,-2.081 ; -3.5,2.081 -3.5,3.3 3.48,3.3 3.5,3.28 ; 3.5,2.081 3.5,3.3
Mechanical 1:
  circle w0.06: c-3.5,-3.3 r0.03
3D body "C408460_MWSA0605S-R68MT_d792f813.step": height 3.1, standoff 0, extent -3.373,-3.555 3.627,3.046

## C2856238_WDFN-6_L3_0-W3_0-P0_95 [mm] "SY6301DSC [C2856238]"
pads (7):
  rrect0% 0.49x0.91 smd: 1(-0.95,-1.53) 2(0,-1.53) 3(0.95,-1.53) 4(0.95,1.53) 5(0,1.53) 6(-0.95,1.53)
  rect 2.1x1.6 smd: 7(0,0)
Top Overlay:
  circle w0.175: c-0.95,-2.285 r0.088
  lines w0.152: -1.385,-1.576 -1.576,-1.576 ; -1.385,1.576 -1.576,1.576 ; 1.385,-1.576 1.576,-1.576 ; 1.385,1.576 1.576,1.576 ; -1.576,-1.576 -1.576,-1.576 ; -1.576,-1.576 -1.576,1.576 ; -1.576,1.576 -1.576,1.576 ; 1.576,-1.576 1.576,-1.576 ; 1.576,-1.576 1.576,1.576 ; 1.576,1.576 1.576,1.576
Mechanical 1:
  circle w0.06: c-1.5,-1.5 r0.03
Mechanical 2:
  circle w0.175: c-0.95,-1.8 r0.088

## C29779868_VQFN-18_L3_5-W3_5-P0_ [mm] "TMI32120 [C29779868]"
pads (18):
  rect 0.3x0.6 smd: 1(-0.787,-1.65) 12(-0.787,1.65)
  rect 0.4x1.15 smd: 2(-0.212,-1.375) 11(-0.212,1.375)
  rect 0.3x1.15 smd: 3(0.438,-1.375) 4(0.988,-1.375) 5(1.537,-1.375) 8(1.537,1.375) 9(0.988,1.375) 10(0.438,1.375)
  rect 2.6x0.3 smd: 6(0.76,-0.3) 7(0.76,0.3)
  rect 0.6x0.25 smd: 13(-1.537,1.25) 14(-1.537,0.75) 15(-1.537,0.25) 16(-1.537,-0.25) 17(-1.537,-0.75) 18(-1.537,-1.25)
Top Overlay:
  circle w0.2: c-1.3,-2.1 r0.1
  lines w0.152: -1.7,1.555 -1.7,1.8 -1.118,1.8 ; 1.868,-1.8 1.9,-1.8 1.9,-0.605 ; 1.868,1.8 1.9,1.8 1.9,0.605 ; 1.9,-0.045 1.9,0.045 ; -1.7,-1.8 -1.118,-1.8 -1.118,-1.555 -1.7,-1.555 -1.7,-1.8
Mechanical 1:
  circle w0.06: c-1.637,-1.75 r0.03
Mechanical 2:
  circle w0.2: c-0.8,-1.9 r0.1

## CAP-SMD_BD6.3-L6.6-W6.6-LS7.3-FD [mm]
pads (2):
  rect 3.5x1.199 smd: 1(-2.67,0) 2(2.67,0)
Top Overlay:
  region: 3.101,-1.42 3.101,-1.618 2.311,-1.618 2.311,-1.42
  region: -3.101,-1.42 -3.101,-1.618 -2.309,-1.618 -2.309,-1.42
  region: -2.804,-0.859 -2.804,-2.177 -2.606,-2.177 -2.606,-0.859
  lines w0.152: -3.376,0.686 -3.376,1.981 -1.979,3.376 3.376,3.376 3.371,0.709 ; -3.363,-0.686 -3.376,-1.981 -1.981,-3.376 3.376,-3.376 3.355,-0.739
Mechanical 2:
  region: 3.101,0.099 3.101,-0.099 2.311,-0.099 2.311,0.099
  region: -3.101,0.099 -3.101,-0.099 -2.309,-0.099 -2.309,0.099
  region: -2.804,0.66 -2.804,-0.66 -2.606,-0.66 -2.606,0.66
Mechanical 6:
  lines w0.051: -3.299,-1.981 -3.299,1.981 -1.979,3.299 3.299,3.299 3.299,-3.299 -1.979,-3.299 -3.299,-1.981
Mechanical 8:
  region: -3.592,-3.299 -3.602,-3.332 -3.627,-3.355 -3.66,-3.36 -3.691,-3.345 -3.708,-3.317 -3.708,-3.284 -3.691,-3.254 -3.66,-3.241 -3.627,-3.246 -3.602,-3.266
Mechanical 9:
  region: -3.65,0.351 -1.001,0.351 -1.001,-0.351 -3.65,-0.351
  region: 0.998,0.351 3.65,0.351 3.65,-0.351 0.998,-0.351
3D body "CAP-SMD_BD6.3-L6.6-W6.6-LS7.3-FD.step": height 5.8, standoff -0.02, extent -3.753,-3.331 3.547,3.27

## CAP-SMD_BD6.3-L6.6-W6.6-LS7.3-FD-H7.7 [mm]
pads (2):
  rect 3.5x1.199 smd: 1(-2.67,0) 2(2.67,0)
Top Overlay:
  region: 3.101,-1.42 3.101,-1.618 2.311,-1.618 2.311,-1.42
  region: -3.101,-1.42 -3.101,-1.618 -2.309,-1.618 -2.309,-1.42
  region: -2.804,-0.859 -2.804,-2.177 -2.606,-2.177 -2.606,-0.859
  lines w0.152: -3.376,0.686 -3.376,1.981 -1.979,3.376 3.376,3.376 3.371,0.709 ; -3.363,-0.686 -3.376,-1.981 -1.981,-3.376 3.376,-3.376 3.355,-0.739
Mechanical 2:
  region: 3.101,0.099 3.101,-0.099 2.311,-0.099 2.311,0.099
  region: -3.101,0.099 -3.101,-0.099 -2.309,-0.099 -2.309,0.099
  region: -2.804,0.66 -2.804,-0.66 -2.606,-0.66 -2.606,0.66
Mechanical 6:
  lines w0.051: -3.299,-1.981 -1.979,-3.299 3.299,-3.299 3.299,3.299 -1.979,3.299 -3.299,1.981 -3.299,-1.981
Mechanical 8:
  region: -3.592,-3.299 -3.602,-3.332 -3.627,-3.355 -3.66,-3.36 -3.691,-3.345 -3.708,-3.317 -3.708,-3.284 -3.691,-3.254 -3.66,-3.241 -3.627,-3.246 -3.602,-3.266
Mechanical 9:
  region: -3.65,0.351 -1.001,0.351 -1.001,-0.351 -3.65,-0.351
  region: 0.998,0.351 3.65,0.351 3.65,-0.351 0.998,-0.351
3D body "CAP-SMD_BD6.3-L6.6-W6.6-LS7.3-FD.step": height 5.8, standoff -0.02, extent -3.65,-3.174 3.65,3.427

## CAP-TH_BD10.0-P5.00-D0.6-FD_2 [mil]
pads (2):
  round 63 hole 39.4: 1(-98.4,0) 2(98.4,0)
Top Overlay:
  region: 140,140 140,-140 170,-100 190,-40 200,20 190,60
  lines w10: -180,0 -140,0 ; -160,-30 -160,30 ; -196.7,-6.2 -196.7,6.3 -195.9,18.7 -194.4,31.1 -192,43.4 -188.9,55.5 -185,67.3 -180.3,78.9 -175,90.2 -168.9,101.1 -162.1,111.6 -154.7,121.7 -146.7,131.3 -138.1,140.3 -128.9,148.8 -119.2,156.7 -109,163.9 -98.4,170.5 -87.4,176.4 -76,181.6 -64.4,186 -52.4,189.7 -40.3,192.7 -28,194.9 -15.6,196.2 -3.1,196.8 9.4,196.6 21.8,195.6 34.2,193.9 46.4,191.3 58.5,188 70.3,183.9 81.8,179.1 93,173.5 103.8,167.3 114.2,160.4 124.1,152.8 133.6,144.6 142.5,135.9 150.8,126.5 158.5,116.7 165.6,106.4 172,95.7 177.8,84.6 182.8,73.2 187,61.4 190.6,49.4 193.3,37.3 195.3,24.9 196.5,12.5 196.9,0 196.5,-12.5 195.3,-24.9 193.3,-37.2 190.6,-49.4 187,-61.4 182.8,-73.2 177.8,-84.6 172,-95.7 165.6,-106.4 158.5,-116.7 150.8,-126.5 142.5,-135.8 133.6,-144.6 124.1,-152.8 114.2,-160.3 103.8,-167.3 93,-173.5 81.8,-179.1 70.3,-183.9 58.5,-188 46.4,-191.3 34.2,-193.8 21.8,-195.6 9.4,-196.6 -3.1,-196.8 -15.6,-196.2 -28,-194.8 -40.3,-192.7 -52.4,-189.7 -64.4,-186 -76,-181.6 -87.4,-176.4 -98.4,-170.5 -109,-163.9 -119.2,-156.6 -128.9,-148.8 -138.1,-140.3 -146.7,-131.2 -154.7,-121.7 -162.1,-111.6 -168.9,-101.1 -175,-90.2 -180.3,-78.9 -185,-67.3 -188.9,-55.4 -192,-43.4 -194.4,-31.1 -195.9,-18.7 -196.7,-6.2
Mechanical 2:
  region: -70,-30 -70,-80 -60,-80 -60,-10 -70,-10
  region: -100,-40 -30,-40 -30,-50 -100,-50
Mechanical 6:
  lines w2: -196.9,0 ccw(c0,0) 196.9,0 ccw(c0,0) -196.9,0
Mechanical 8:
  region: -194.5,-196.8 -194.9,-198.1 -195.9,-199 -197.2,-199.2 -198.4,-198.6 -199.1,-197.5 -199.1,-196.2 -198.4,-195.1 -197.2,-194.5 -195.9,-194.7 -194.9,-195.6
Mechanical 9:
  region: 110.3,0 109.9,-2.9 108.8,-5.7 107.1,-8.1 104.8,-10 102.1,-11.2 99.2,-11.8 96.2,-11.6 93.4,-10.7 90.9,-9.1 88.9,-6.9 87.5,-4.3 86.7,-1.5 86.7,1.5 87.5,4.4 88.9,7 90.9,9.1 93.4,10.7 96.2,11.6 99.2,11.8 102.1,11.2 104.8,10 107.1,8.1 108.8,5.7 109.9,2.9
  region: -86.6,0 -87,-2.9 -88.1,-5.7 -89.8,-8.1 -92.1,-10 -94.8,-11.2 -97.7,-11.8 -100.6,-11.6 -103.4,-10.7 -105.9,-9.1 -108,-6.9 -109.4,-4.3 -110.1,-1.5 -110.1,1.5 -109.4,4.4 -108,7 -105.9,9.1 -103.4,10.7 -100.6,11.6 -97.7,11.8 -94.8,11.2 -92.1,10 -89.8,8.1 -88.1,5.7 -87,2.9

## CAP-TH_BD12.5-P5.00-D0.6-FD [mm]
pads (2):
  round 2.1 hole 1.2 paste-2539.97 mask+0.05: 1(-2.5,0) 2(2.5,0)
Top Overlay:
  circle w0.254: c0,0 r6.25
  region: 3.75,5 3.75,-5 4.482,-4.268 4.715,-4.022 4.933,-3.763 5.137,-3.493 5.325,-3.211 5.497,-2.919 5.652,-2.619 5.79,-2.31 5.911,-1.993 6.014,-1.671 6.099,-1.343 6.165,-1.011 6.212,-0.676 6.24,-0.338 6.25,0 6.24,0.338 6.212,0.676 6.165,1.011 6.099,1.343 6.014,1.671 5.911,1.993 5.79,2.31 5.652,2.619 5.497,2.919 5.325,3.211 5.137,3.493 4.933,3.763 4.715,4.022 4.482,4.268
  lines w0.254: -5.817,0.178 -4.14,0.178 ; -5.004,-0.66 -5.004,1.067
Mechanical 2:
  region: -5.092,-0.811 -5.092,1.189 -4.842,1.189 -4.842,-0.811
  region: -6,0.25 -4,0.25 -4,0 -6,0
Mechanical 6:
  lines w0.051: -6.25,0 ccw(c0,0) 6.25,0 ccw(c0,0) -6.25,0
Mechanical 8:
  region: -6.189,-6.25 -6.189,-6.275 -6.225,-6.311 -6.275,-6.311 -6.311,-6.275 -6.311,-6.25 -6.311,-6.225 -6.275,-6.189 -6.225,-6.189 -6.189,-6.225 -6.189,-6.25 -6.19,-6.25
Mechanical 9:
  region: 2.8,0 2.8,-0.06 2.754,-0.17 2.67,-0.254 2.56,-0.3 2.44,-0.3 2.33,-0.254 2.246,-0.17 2.2,-0.06 2.2,0 2.2,0.06 2.246,0.17 2.33,0.254 2.44,0.3 2.56,0.3 2.67,0.254 2.754,0.17 2.8,0.06 2.8,0
  region: -2.2,0 -2.2,-0.06 -2.246,-0.17 -2.33,-0.254 -2.44,-0.3 -2.56,-0.3 -2.67,-0.254 -2.754,-0.17 -2.8,-0.06 -2.8,0 -2.8,0.06 -2.754,0.17 -2.67,0.254 -2.56,0.3 -2.44,0.3 -2.33,0.254 -2.246,0.17 -2.2,0.06 -2.2,0

## CAP-TH_BD16.0-P7.50-D0.8-FD [mm]
pads (2):
  round 2.2 hole 1.199: 1(-3.749,0) 2(3.752,0)
Top Overlay:
  drawing of 128 lines, arcs and shapes, not listed
Mechanical 2:
  region: 7.701,-0.201 5.415,-0.201 5.415,0.307 7.701,0.307
  region: -6.754,1.852 -6.246,1.852 -6.246,-1.45 -6.754,-1.45
  region: -7.62,0.508 -5.334,0.508 -5.334,0 -7.62,0
Mechanical 6:
  lines w0.051: -8.001,0 cw(c0,0) 8.001,0 cw(c0,0) -8.001,0
Mechanical 8:
  region: -7.94,-7.998 -7.95,-8.031 -7.976,-8.054 -8.009,-8.059 -8.039,-8.044 -8.057,-8.016 -8.057,-7.983 -8.039,-7.955 -8.009,-7.94 -7.976,-7.945 -7.95,-7.968
Mechanical 9:
  region: -3.35,0 -3.36,-0.089 -3.388,-0.173 -3.437,-0.249 -3.5,-0.312 -3.576,-0.361 -3.66,-0.389 -3.749,-0.399 -3.838,-0.389 -3.922,-0.361 -3.998,-0.312 -4.061,-0.249 -4.11,-0.173 -4.14,-0.089 -4.15,0 -4.14,0.089 -4.11,0.175 -4.061,0.249 -3.998,0.312 -3.922,0.361 -3.838,0.391 -3.749,0.401 -3.66,0.391 -3.576,0.361 -3.5,0.312 -3.437,0.249 -3.388,0.175 -3.36,0.089
  region: 4.15,0 4.14,-0.089 4.11,-0.173 4.064,-0.249 4,-0.312 3.924,-0.361 3.84,-0.389 3.752,-0.399 3.663,-0.389 3.576,-0.361 3.5,-0.312 3.439,-0.249 3.391,-0.173 3.36,-0.089 3.35,0 3.36,0.089 3.391,0.175 3.439,0.249 3.5,0.312 3.576,0.361 3.663,0.391 3.752,0.401 3.84,0.391 3.924,0.361 4,0.312 4.064,0.249 4.11,0.175 4.14,0.089

## CAP-TH_L8.0-W4.5-P7.50-D0.6 [mil]
pads (2):
  round 60 hole 31.5 paste-99999 mask+1.97: 1(-147.64,0) 2(147.64,0)
Top Overlay:
  lines w10: -155,-38.4 -155,-90 155,-90 155,-85 155,-38.4 ; -155,38.4 -155,90 155,90 155,38.4
Mechanical 6:
  lines w2: -157.48,-88.58 -157.48,88.58 157.48,88.58 157.48,-88.58 -157.48,-88.58
Mechanical 8:
  region: -157.09,-88.58 -157.09,-89.56 -158.47,-90.94 -160.43,-90.94 -161.81,-89.56 -161.81,-88.58 -161.81,-87.6 -160.43,-86.22 -158.47,-86.22 -157.09,-87.6 -157.09,-88.58
Mechanical 9:
  region: 159.46,0 159.46,-2.35 157.66,-6.69 154.33,-10.02 149.99,-11.82 145.29,-11.82 140.95,-10.02 137.62,-6.69 135.82,-2.35 135.82,0 135.82,2.35 137.62,6.69 140.95,10.02 145.29,11.82 149.99,11.82 154.33,10.02 157.66,6.69 159.46,2.35 159.46,0
  region: -135.82,0 -135.82,-2.35 -137.62,-6.69 -140.95,-10.02 -145.29,-11.82 -149.99,-11.82 -154.33,-10.02 -157.66,-6.69 -159.46,-2.35 -159.46,0 -159.46,2.35 -157.66,6.69 -154.33,10.02 -149.99,11.82 -145.29,11.82 -140.95,10.02 -137.62,6.69 -135.82,2.35 -135.82,0
3D body "CAP-TH_L8.0-W4.5-P7.50-D0.6.step": height 377.48, standoff -193.39, extent -182.17,-97.17 172.17,80

## CONN-SMD_60P-P0.40_HCTL_HC-PBB40C-60DP-0.4V-02 [mm]
pads (64):
  rect 0.23x0.66 smd paste+0 mask+0.05: 1(-5.8,-1.355) 2(-5.8,1.355) 3(-5.4,-1.355) 4(-5.4,1.355) 5(-5,-1.355) 6(-5,1.355) 7(-4.6,-1.355) 8(-4.6,1.355) 9(-4.2,-1.355) 10(-4.2,1.355) 11(-3.8,-1.355) 12(-3.8,1.355) 13(-3.4,-1.355) 14(-3.4,1.355) 15(-3,-1.355) 16(-3,1.355) 17(-2.6,-1.355) 18(-2.6,1.355) 19(-2.2,-1.355) 20(-2.2,1.355) 21(-1.8,-1.355) 22(-1.8,1.355) 23(-1.4,-1.355) 24(-1.4,1.355) 25(-1,-1.355) 26(-1,1.355) 27(-0.6,-1.355) 28(-0.6,1.355) 29(-0.2,-1.355) 30(-0.2,1.355) 31(0.2,-1.355) 32(0.2,1.355) 33(0.6,-1.355) 34(0.6,1.355) 35(1,-1.355) 36(1,1.355) 37(1.4,-1.355) 38(1.4,1.355) 39(1.8,-1.355) 40(1.8,1.355) 41(2.2,-1.355) 42(2.2,1.355) 43(2.6,-1.355) 44(2.6,1.355) 45(3,-1.355) 46(3,1.355) 47(3.4,-1.355) 48(3.4,1.355) 49(3.8,-1.355) 50(3.8,1.355) 51(4.2,-1.355) 52(4.2,1.355) 53(4.6,-1.355) 54(4.6,1.355) 55(5,-1.355) 56(5,1.355) 57(5.4,-1.355) 58(5.4,1.355) 59(5.8,-1.355) 60(5.8,1.355)
  rect 0.35x0.66 smd paste+0 mask+0.05: 61(6.275,1.355) 62(6.275,-1.355) 63(-6.275,-1.355) 64(-6.275,1.355)
Top Overlay:
  circle w0.254: c-5.81,-2.413 r0.127
  lines w0.15: -6.598,-0.925 -6.76,-0.925 -6.76,0.925 -6.598,0.925 ; 6.598,-0.925 6.76,-0.925 6.76,0.925 6.598,0.925
Mechanical 6:
  lines w0.051: -6.76,-0.925 -6.76,0.925 6.76,0.925 6.76,-0.925 -6.76,-0.925
Mechanical 7:
  drawing of 64 lines, arcs and shapes, not listed
Mechanical 8:
  region: -6.7,-1.485 -6.7,-1.51 -6.735,-1.545 -6.785,-1.545 -6.82,-1.51 -6.82,-1.485 -6.82,-1.46 -6.785,-1.425 -6.735,-1.425 -6.7,-1.46 -6.7,-1.485
Mechanical 9:
  drawing of 64 lines, arcs and shapes, not listed
3D body "CONN-SMD_60P-P0.40_HCTL_HC-PBB40C-60DP-0.4V-02.step": height 1.17, standoff 0.03, extent -6.804,-1.523 6.726,1.447

## CONN-SMD_120P-P0.40_DF40C-120DP-0.4V-51 [mm]
pads (124):
  rect 0.2x0.66 smd paste+0 mask+0.05: 1(-11.8,-1.355) 2(-11.8,1.355) 3(-11.4,-1.355) 4(-11.4,1.355) 5(-11,-1.355) 6(-11,1.355) 7(-10.6,-1.355) 8(-10.6,1.355) 9(-10.2,-1.355) 10(-10.2,1.355) 11(-9.8,-1.355) 12(-9.8,1.355) 13(-9.4,-1.355) 14(-9.4,1.355) 15(-9,-1.355) 16(-9,1.355) 17(-8.6,-1.355) 18(-8.6,1.355) 19(-8.2,-1.355) 20(-8.2,1.355) 21(-7.8,-1.355) 22(-7.8,1.355) 23(-7.4,-1.355) 24(-7.4,1.355) 25(-7,-1.355) 26(-7,1.355) 27(-6.6,-1.355) 28(-6.6,1.355) 29(-6.2,-1.355) 30(-6.2,1.355) 31(-5.8,-1.355) 32(-5.8,1.355) 33(-5.4,-1.355) 34(-5.4,1.355) 35(-5,-1.355) 36(-5,1.355) 37(-4.6,-1.355) 38(-4.6,1.355) 39(-4.2,-1.355) 40(-4.2,1.355) 41(-3.8,-1.355) 42(-3.8,1.355) 43(-3.4,-1.355) 44(-3.4,1.355) 45(-3,-1.355) 46(-3,1.355) 47(-2.6,-1.355) 48(-2.6,1.355) 49(-2.2,-1.355) 50(-2.2,1.355) 51(-1.8,-1.355) 52(-1.8,1.355) 53(-1.4,-1.355) 54(-1.4,1.355) 55(-1,-1.355) 56(-1,1.355) 57(-0.6,-1.355) 58(-0.6,1.355) 59(-0.2,-1.355) 60(-0.2,1.355) 61(0.2,-1.355) 62(0.2,1.355) 63(0.6,-1.355) 64(0.6,1.355) 65(1,-1.355) 66(1,1.355) 67(1.4,-1.355) 68(1.4,1.355) 69(1.8,-1.355) 70(1.8,1.355) 71(2.2,-1.355) 72(2.2,1.355) 73(2.6,-1.355) 74(2.6,1.355) 75(3,-1.355) 76(3,1.355) 77(3.4,-1.355) 78(3.4,1.355) 79(3.8,-1.355) 80(3.8,1.355) 81(4.2,-1.355) 82(4.2,1.355) 83(4.6,-1.355) 84(4.6,1.355) 85(5,-1.355) 86(5,1.355) 87(5.4,-1.355) 88(5.4,1.355) 89(5.8,-1.355) 90(5.8,1.355) 91(6.2,-1.355) 92(6.2,1.355) 93(6.6,-1.355) 94(6.6,1.355) 95(7,-1.355) 96(7,1.355) 97(7.4,-1.355) 98(7.4,1.355) 99(7.8,-1.355) 100(7.8,1.355) 101(8.2,-1.355) 102(8.2,1.355) 103(8.6,-1.355) 104(8.6,1.355) 105(9,-1.355) 106(9,1.355) 107(9.4,-1.355) 108(9.4,1.355) 109(9.8,-1.355) 110(9.8,1.355) 111(10.2,-1.355) 112(10.2,1.355) 113(10.6,-1.355) 114(10.6,1.355) 115(11,-1.355) 116(11,1.355) 117(11.4,-1.355) 118(11.4,1.355) 119(11.8,-1.355) 120(11.8,1.355)
  rect 0.3x0.66 smd paste+0 mask+0.05: 121(12.265,-1.355) 122(12.265,1.355) 123(-12.265,-1.355) 124(-12.265,1.355)
Top Overlay:
  lines w0.254: -12.634,0.95 -12.75,0.95 -12.75,-0.9 -12.609,-0.9 ; 12.609,-0.9 12.75,-0.9 12.75,0.9 ; 12.634,0.95 12.75,0.95
Mechanical 6:
  lines w0.051: -12.75,-0.925 12.75,-0.925 12.75,0.925 -12.75,0.925 -12.75,-0.925
Mechanical 7:
  drawing of 124 lines, arcs and shapes, not listed
Mechanical 8:
  region: -12.69,-1.485 -12.69,-1.51 -12.725,-1.545 -12.775,-1.545 -12.81,-1.51 -12.81,-1.485 -12.81,-1.46 -12.775,-1.425 -12.725,-1.425 -12.69,-1.46 -12.69,-1.485
Mechanical 9:
  drawing of 124 lines, arcs and shapes, not listed
3D body "CONN-SMD_120P-P0.40_DF40C-120DP-0.4V-51.step": height 1.07, standoff -0.08, extent -12.765,-1.524 12.765,1.446

## CONN-SMD_DF40C-40DP-0.4V [mm]
pads (44):
  rect 0.19x0.75 smd: 1(-3.8,-1.455) 2(-3.8,1.455) 3(-3.4,-1.455) 4(-3.4,1.455) 5(-3,-1.455) 6(-3,1.455) 7(-2.6,-1.455) 8(-2.6,1.455) 9(-2.2,-1.455) 10(-2.2,1.455) 11(-1.8,-1.455) 12(-1.8,1.455) 13(-1.4,-1.455) 14(-1.4,1.455) 15(-1,-1.455) 16(-1,1.455) 17(-0.6,-1.455) 18(-0.6,1.455) 19(-0.2,-1.455) 20(-0.2,1.455) 21(0.2,-1.455) 22(0.2,1.455) 23(0.6,-1.455) 24(0.6,1.455) 25(1,-1.455) 26(1,1.455) 27(1.4,-1.455) 28(1.4,1.455) 29(1.8,-1.455) 30(1.8,1.455) 31(2.2,-1.455) 32(2.2,1.455) 33(2.6,-1.455) 34(2.6,1.455) 35(3,-1.455) 36(3,1.455) 37(3.4,-1.455) 38(3.4,1.455) 39(3.8,-1.455) 40(3.8,1.455)
  rect 0.35x0.75 smd: 41(4.275,-1.455) 42(4.275,1.455) 43(-4.275,1.455) 44(-4.275,-1.455)
Top Overlay:
  region: -5,-1.7 -4.6,-1.7 -4.8,-1.2
  lines w0.254: -4.67,-1 -4.8,-1 -4.8,1 -4.67,1 ; 4.696,-0.984 4.826,-0.984 4.826,1.016 4.696,1.016 ; -4,-0.635 -4,0.6 4.064,0.6 4.064,-0.635 -4,-0.635 ; -3.048,-0.146 -3.048,0.254 -1.048,0.254 -1.048,-0.146 -3.048,-0.146 ; 1.016,-0.146 1.016,0.254 3.016,0.254 3.016,-0.146 1.016,-0.146
Mechanical 2:
  region: -4.8,-1.19 -4.8,-1.5 -5,-1.7
  region: -4.8,-1.19 -4.8,-1.5 -5,-1.7 -4.6,-1.7
Mechanical 6:
  lines w0.051: -4.76,-0.925 -4.76,0.925 4.76,0.925 4.76,-0.925 -4.76,-0.925
Mechanical 7:
  drawing of 44 lines, arcs and shapes, not listed
Mechanical 8:
  region: -4.7,-1.485 -4.7,-1.51 -4.735,-1.545 -4.785,-1.545 -4.82,-1.51 -4.82,-1.485 -4.82,-1.46 -4.785,-1.425 -4.735,-1.425 -4.7,-1.46 -4.7,-1.485
Mechanical 9:
  drawing of 44 lines, arcs and shapes, not listed
3D body "CONN-SMD_DF40C-40DP-0.4V.step": height 1.16, standoff 0, extent -4.761,-1.485 4.76,1.485

## CONN-SMD_DF40C-70DP-0.4V-51 [mm]
pads (74):
  rect 0.23x1 smd: 1(-6.794,-1.355) 2(-6.394,-1.355) 3(-5.995,-1.355) 4(-5.595,-1.355) 5(-5.195,-1.355) 6(-4.795,-1.355) 7(-4.394,-1.355) 8(-3.995,-1.355) 9(-3.595,-1.355) 10(-3.195,-1.355) 11(-2.795,-1.355) 12(-2.394,-1.355) 13(-1.995,-1.355) 14(-1.595,-1.355) 15(-1.195,-1.355) 16(-0.795,-1.355) 17(-0.394,-1.355) 18(0.005,-1.355) 19(0.405,-1.355) 20(0.805,-1.355) 21(1.205,-1.355) 22(1.606,-1.355) 23(2.005,-1.355) 24(2.405,-1.355) 25(2.805,-1.355) 26(3.205,-1.355) 27(3.606,-1.355) 28(4.005,-1.355) 29(4.405,-1.355) 30(4.805,-1.355) 31(5.205,-1.355) 32(5.606,-1.355) 33(6.005,-1.355) 34(6.405,-1.355) 35(6.805,-1.355) 36(6.794,1.355) 37(6.394,1.355) 38(5.994,1.355) 39(5.594,1.355) 40(5.195,1.355) 41(4.786,1.355) 42(4.386,1.355) 43(3.987,1.355) 44(3.586,1.355) 45(3.186,1.355) 46(2.786,1.355) 47(2.386,1.355) 48(1.986,1.355) 49(1.586,1.355) 50(1.186,1.355) 51(0.786,1.355) 52(0.386,1.355) 53(-0.014,1.355) 54(-0.414,1.355) 55(-0.814,1.355) 56(-1.214,1.355) 57(-1.614,1.355) 58(-2.014,1.355) 59(-2.414,1.355) 60(-2.814,1.355) 61(-3.214,1.355) 62(-3.614,1.355) 63(-4.014,1.355) 64(-4.414,1.355) 65(-4.814,1.355) 66(-5.214,1.355) 67(-5.614,1.355) 68(-6.014,1.355) 69(-6.413,1.355) 70(-6.794,1.355)
  rect 0.35x1 smd: 71(-7.269,1.355) 72(-7.269,-1.355) 73(7.269,-1.355) 74(7.269,1.355)
Top Overlay:
  circle w0.254: c-8.195,-1.6 r0.127
  lines w0.254: -7.676,-0.925 -7.755,-0.925 -7.755,0.925 -7.676,0.925 ; 7.668,-0.925 7.747,-0.925 7.747,0.925 7.668,0.925
Mechanical 4:
  lines w0.051: -7.76,-0.925 7.76,-0.925 7.76,0.925 -7.76,0.925 -7.76,-0.925
Mechanical 6:
  region: -7.7,-1.485 -7.7,-1.51 -7.735,-1.545 -7.785,-1.545 -7.82,-1.51 -7.82,-1.485 -7.82,-1.46 -7.785,-1.425 -7.735,-1.425 -7.7,-1.46 -7.7,-1.485
Mechanical 7:
  drawing of 74 lines, arcs and shapes, not listed
3D body "CONN-SMD_DF40C-70DP-0.4V-51.step": height 1.2, standoff 0, extent -7.747,-1.612 7.774,1.358

## CONN-SMD_DF40C-80DP-0.4V-51 [mm]
pads (84):
  rect 0.2x1 smd: 1(-7.8,-1.355) 2(-7.4,-1.355) 3(-7,-1.355) 4(-6.6,-1.355) 5(-6.2,-1.355) 6(-5.8,-1.355) 7(-5.4,-1.355) 8(-5,-1.355) 9(-4.6,-1.355) 10(-4.2,-1.355) 11(-3.8,-1.355) 12(-3.4,-1.355) 13(-3,-1.355) 14(-2.6,-1.355) 15(-2.2,-1.355) 16(-1.8,-1.355) 17(-1.4,-1.355) 18(-1,-1.355) 19(-0.6,-1.355) 20(-0.2,-1.355) 21(0.2,-1.355) 22(0.6,-1.355) 23(1,-1.355) 24(1.4,-1.355) 25(1.8,-1.355) 26(2.2,-1.355) 27(2.6,-1.355) 28(3,-1.355) 29(3.4,-1.355) 30(3.8,-1.355) 31(4.2,-1.355) 32(4.6,-1.355) 33(5,-1.355) 34(5.4,-1.355) 35(5.8,-1.355) 36(6.2,-1.355) 37(6.6,-1.355) 38(7,-1.355) 39(7.4,-1.355) 40(7.8,-1.355) 41(7.8,1.355) 42(7.4,1.355) 43(7,1.355) 44(6.6,1.355) 45(6.2,1.355) 46(5.8,1.355) 47(5.4,1.355) 48(5,1.355) 49(4.6,1.355) 50(4.2,1.355) 51(3.8,1.355) 52(3.4,1.355) 53(3,1.355) 54(2.6,1.355) 55(2.2,1.355) 56(1.8,1.355) 57(1.4,1.355) 58(1,1.355) 59(0.6,1.355) 60(0.2,1.355) 61(-0.2,1.355) 62(-0.6,1.355) 63(-1,1.355) 64(-1.4,1.355) 65(-1.8,1.355) 66(-2.2,1.355) 67(-2.6,1.355) 68(-3,1.355) 69(-3.4,1.355) 70(-3.8,1.355) 71(-4.2,1.355) 72(-4.6,1.355) 73(-5,1.355) 74(-5.4,1.355) 75(-5.8,1.355) 76(-6.2,1.355) 77(-6.6,1.355) 78(-7,1.355) 79(-7.4,1.355) 80(-7.8,1.355)
  rect 0.35x1 smd: 81(-8.275,1.355) 82(-8.275,-1.355) 83(8.275,-1.355) 84(8.275,1.355)
Top Overlay:
  circle w0.254: c-9.2,-1.6 r0.127
  lines w0.254: -8.681,-1.5 -8.76,-1.5 -8.76,1.5 -8.681,1.5 ; 8.681,-1.5 8.76,-1.5 8.76,1.5 8.681,1.5
Mechanical 6:
  lines w0.051: -8.76,-0.925 8.76,-0.925 8.76,0.925 -8.76,0.925 -8.76,-0.925
Mechanical 8:
  region: -8.7,-1.485 -8.7,-1.51 -8.735,-1.545 -8.785,-1.545 -8.82,-1.51 -8.82,-1.485 -8.82,-1.46 -8.785,-1.425 -8.735,-1.425 -8.7,-1.46 -8.7,-1.485
Mechanical 9:
  drawing of 84 lines, arcs and shapes, not listed
3D body "CONN-SMD_DF40C-80DP-0.4V-51.step": height 1.24, standoff 0, extent -8.761,-1.485 8.76,1.485

## CONN-TH_3P-P2.54_2501S-3P [mm]
pads (3):
  rect 1.6x1.6 hole 1: 1(-2.54,0)
  round 1.6 hole 1: 2(0,0) 3(2.54,0)
Top Overlay:
  lines w0.254: -2.794,-2.35 -2.794,-1.524 ; -2.279,-2.35 -2.279,-1.524 ; 2.268,-2.35 2.268,-1.524 ; 2.751,-2.35 2.751,-1.524 ; -4.98,-2.35 -4.98,3.35 5.02,3.35 5.02,-2.35 -4.98,-2.35 ; -4.318,-1.524 4.318,-1.524 4.318,2.54 -4.318,2.54 -4.318,-1.524
Mechanical 2:
  region: -2.22,-2.3 2.098,-2.3 2.098,-1.538 -2.22,-1.538
  region: 2.794,-2.286 2.794,-1.524 4.318,-1.524 4.318,2.54 -4.318,2.54 -4.318,-1.524 -2.794,-1.524 -2.794,-2.286 -5.08,-2.286 -5.08,3.302 5.08,3.302 5.08,-2.286
Mechanical 6:
  lines w0.051: -5,-2.5 -5,3.4 5,3.4 5,-2.5 -5,-2.5
Mechanical 8:
  region: -4.94,3.4 -4.94,3.375 -4.975,3.34 -5.025,3.34 -5.06,3.375 -5.06,3.4 -5.06,3.425 -5.025,3.46 -4.975,3.46 -4.94,3.425 -4.94,3.4
Mechanical 9:
  region: 2.215,0.325 2.865,0.325 2.865,-0.325 2.215,-0.325
  region: -0.325,0.325 0.325,0.325 0.325,-0.325 -0.325,-0.325
  region: -2.865,0.325 -2.215,0.325 -2.215,-0.325 -2.865,-0.325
